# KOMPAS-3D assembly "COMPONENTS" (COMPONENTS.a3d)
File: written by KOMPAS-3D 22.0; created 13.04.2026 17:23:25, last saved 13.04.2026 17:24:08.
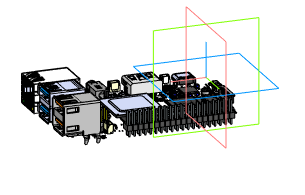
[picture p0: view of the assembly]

Document properties: Автор: Andrey; Полное имя файла: C:\Users\User1\Documents\Работа\Корпуса\Корпус Repka Pi 5\Конструкторская документация\3д модель\Repka_5_3D\COMPONENTS.a3d

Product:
- Component [assembly]: C0201  | qty 1  | source file: C0201.a3d
- Component [assembly]: C0201  | qty 293  | Комментарий: C0201; source file: C0201.a3d
- Component [assembly]: QFN50P500X500X90-33N-D  | qty 1  | Масса: 0.000177; source file: QFN50P500X500X90-33N-D.a3d
- Component [assembly]: QFN45P400X400X80-29N  | qty 1  | Масса: 0.00011; source file: QFN45P400X400X80-29N.a3d
- Component [assembly]: QFN40P500X500X90-41N  | qty 1  | Масса: 0.000173; source file: QFN40P500X500X90-41N.a3d
- Component [assembly]: JST_BM03B-SRSS-TBLFSN  | qty 1  | Масса: 0.000249; source file: JST_BM03B-SRSS-TBLFSN.a3d
- Component [assembly]: L2520  | qty 1  | Масса: 0.000033; source file: L2520.a3d
- Component [assembly]: L2520  | qty 8  | Масса: 0.000033; Комментарий: L2520; source file: L2520.a3d
- Component [assembly]: IND_201610  | qty 1  | Масса: 0.000025; source file: IND_201610.a3d
- Component [assembly]: IND_201610  | qty 5  | Масса: 0.000025; Комментарий: IND_201610; source file: IND_201610.a3d
- Component [assembly]: IND_404020  | qty 1  | Масса: 0.0002; source file: IND_404020.a3d
- Component [assembly]: C0603  | qty 1  | Масса: 0.000009; source file: C0603.a3d
- Component [assembly]: C0603  | qty 77  | Масса: 0.000009; Комментарий: C0603; source file: C0603.a3d
- Component [assembly]: SUNTECH_ST-TF-003A  | qty 1  | Масса: 0.001552; source file: SUNTECH_ST-TF-003A.a3d
- Component [assembly]: R0201  | qty 1  | source file: R0201.a3d
- Component [assembly]: R0201  | qty 213  | Комментарий: R0201; source file: R0201.a3d
- Component [assembly]: R0603  | qty 1  | Масса: 0.000004; source file: R0603.a3d
- Component [assembly]: R0603  | qty 1  | Масса: 0.000004; Комментарий: R0603; source file: R0603.a3d
- Component [assembly]: C0402  | qty 1  | Масса: 0.000002; source file: C0402.a3d
- Component [assembly]: C0402  | qty 76  | Масса: 0.000002; Комментарий: C0402; source file: C0402.a3d
- Component [assembly]: C0805  | qty 1  | Масса: 0.000027; source file: C0805.a3d
- Component [assembly]: C0805  | qty 7  | Масса: 0.000027; Комментарий: C0805; source file: C0805.a3d
- Component [assembly]: HR911130C  | qty 1  | Масса: 0.029144; source file: HR911130C.a3d
- Component [assembly]: SOT-323  | qty 1  | Масса: 0.000021; source file: SOT-323.a3d
- Component [assembly]: SOT-323  | qty 8  | Масса: 0.000021; Комментарий: SOT-323; source file: SOT-323.a3d
- Component [assembly]: BGA20C40P4X5_161X201X63  | qty 1  | Масса: 0.000011; source file: BGA20C40P4X5_161X201X63.a3d
- Component [assembly]: BGA20C40P4X5_161X201X63  | qty 2  | Масса: 0.000011; Комментарий: BGA20C40P4X5_161X201X63; source file: BGA20C40P4X5_161X201X63.a3d
- Component [assembly]: NX2016SA  | qty 1  | Масса: 0.000012; source file: NX2016SA.a3d
- Component [assembly]: NX2016SA  | qty 3  | Масса: 0.000012; Комментарий: NX2016SA; source file: NX2016SA.a3d
- Component [assembly]: BGA1088_23R00X23R00X2R00  | qty 1  | Масса: 0.006277; source file: BGA1088_23R00X23R00X2R00.a3d
- Component [assembly]: BGA200C65X80P22X12_1500X1000X114N  | qty 1  | Масса: 0.00091; source file: BGA200C65X80P22X12_1500X1000X114N.a3d
- Component [assembly]: BGA200C65X80P22X12_1500X1000X114N  | qty 1  | Масса: 0.00091; Комментарий: BGA200C65X80P22X12_1500X1000X114N; source file: BGA200C65X80P22X12_1500X1000X114N.a3d
- Component [assembly]: SOD_323  | qty 1  | Масса: 0.000016; source file: SOD_323.a3d
- Component [assembly]: SOD_323  | qty 6  | Масса: 0.000016; Комментарий: SOD_323; source file: SOD_323.a3d
- Component [assembly]: XTAL_NX3215SA-32768K-STD-MUA-8  | qty 1  | Масса: 0.000032; source file: XTAL_NX3215SA-32768K-STD-MUA-8.a3d
- Component [assembly]: SOP65P490X110-8N  | qty 1  | Масса: 0.00007; source file: SOP65P490X110-8N.a3d
- Component [detail]: SW_SMD_3_4_2  | qty 1  | Комментарий: SW_SMD_3_4_2; source file: SW_SMD_3_4_2.m3d
- Component [assembly]: SOT_23_5  | qty 1  | Масса: 0.000046; source file: SOT_23_5.a3d
- Component [assembly]: SOT_23_5  | qty 2  | Масса: 0.000046; Комментарий: SOT_23_5; source file: SOT_23_5.a3d
- Component [assembly]: L0402  | qty 1  | Масса: 0.000002; source file: L0402.a3d
- Component [detail]: TEST_POINT_060  | qty 10  | Комментарий: TEST_POINT_060; source file: TEST_POINT_060.m3d
- Component [detail]: TEST_POINT_080  | qty 14  | Комментарий: TEST_POINT_080; source file: TEST_POINT_080.m3d
- Component [assembly]: QFN68_7R00X7R00X0R80_T  | qty 1  | Масса: 0.000332; source file: QFN68_7R00X7R00X0R80_T.a3d
- Component [assembly]: GCT_FFC2A33-22-T-R_REVA  | qty 1  | Масса: 0.001036; source file: GCT_FFC2A33-22-T-R_REVA.a3d
- Component [assembly]: GCT_FFC2A33-22-T-R_REVA  | qty 1  | Масса: 0.001036; Комментарий: GCT_FFC2A33-22-T-R_REVA; source file: GCT_FFC2A33-22-T-R_REVA.a3d
- Component [assembly]: CUI_UJC-HP-3-SMT-TR  | qty 1  | Масса: 0.000312; source file: CUI_UJC-HP-3-SMT-TR.a3d
- Component [assembly]: HDMI_SMD  | qty 1  | Масса: 0.004704; source file: HDMI_SMD.a3d
- Component [assembly]: GB042-30-34PH10  | qty 1  | Масса: 0.00023; source file: GB042-30-34PH10.a3d
- Component [assembly]: SAMTEC_USBR-A-D-F-O-TH  | qty 1  | Масса: 0.021096; source file: SAMTEC_USBR-A-D-F-O-TH.a3d
- Component [assembly]: BGA153_PAD30  | qty 1  | Масса: 0.000515; source file: BGA153_PAD30.a3d
- Component [assembly]: ESD0402  | qty 1  | Масса: 0.000002; source file: ESD0402.a3d
- Component [assembly]: ESD0402  | qty 17  | Масса: 0.000002; Комментарий: ESD0402; source file: ESD0402.a3d
- Component [assembly]: 1188E1K2QTR  | qty 1  | Масса: 0.000327; source file: 1188E1K2QTR.a3d
- Component [assembly]: MOLEX_48406-0003  | qty 1  | Масса: 0.017886; source file: MOLEX_48406-0003.a3d
- Component [assembly]: LED0603  | qty 1  | Масса: 0.000005; source file: LED0603.a3d
- Component [assembly]: LED0603  | qty 1  | Масса: 0.000005; Комментарий: LED0603; source file: LED0603.a3d
- Component [assembly]: JST_BM02B-SRSS-TBLFSN  | qty 1  | Масса: 0.00021; source file: JST_BM02B-SRSS-TBLFSN.a3d
- Component [assembly]: AP6210  | qty 1  | Масса: 0.001822; source file: AP6210.a3d
- Component [assembly]: SON127P500X600X80-9N  | qty 1  | Масса: 0.000183; source file: SON127P500X600X80-9N.a3d
- Component [assembly]: GCT_FFC2A33-16-T-R_REVA  | qty 1  | Масса: 0.000865; source file: GCT_FFC2A33-16-T-R_REVA.a3d
- Component [detail]: JST_B4B-PH-K-SLFSN  | qty 1  | Масса: 0.001556; source file: JST_B4B-PH-K-SLFSN.m3d
- Component [detail]: JST_B4B-PH-K-SLFSN  | qty 1  | Масса: 0.001556; Комментарий: JST_B4B-PH-K-SLFSN; source file: JST_B4B-PH-K-SLFSN.m3d
- Component [assembly]: SAMTEC_HTSW-102-26-L-D  | qty 1  | Масса: 0.000525; source file: SAMTEC_HTSW-102-26-L-D.a3d
- Component [assembly]: JST_BM04B-SRSS-TBLFSN  | qty 1  | Масса: 0.000287; source file: JST_BM04B-SRSS-TBLFSN.a3d
- Component [assembly]: HRS_UFL-R-SMT01  | qty 1  | Масса: 0.000027; source file: HRS_UFL-R-SMT01.a3d
- Component [assembly]: PJ3420ASMT  | qty 1  | Масса: 0.001673; source file: PJ3420ASMT.a3d
- Component [assembly]: PIN_40_254  | qty 1  | Масса: 0.006833; source file: PIN_40_254.a3d
- Part/product: COMPONENTS
    Масса: 0.10509
    Комментарий: COMPONENTS

Referenced files in C:\Users\User1\Documents\Работа\Корпуса\Корпус Repka Pi 5\Конструкторская документация\3д модель\Repka_5_3D\: C0201.a3d, QFN50P500X500X90-33N-D.a3d, QFN45P400X400X80-29N.a3d, QFN40P500X500X90-41N.a3d, JST_BM03B-SRSS-TBLFSN.a3d, L2520.a3d, IND_201610.a3d, IND_404020.a3d, C0603.a3d, SUNTECH_ST-TF-003A.a3d, R0201.a3d, R0603.a3d, C0402.a3d, C0805.a3d, HR911130C.a3d, SOT-323.a3d, BGA20C40P4X5_161X201X63.a3d, NX2016SA.a3d, BGA1088_23R00X23R00X2R00.a3d, BGA200C65X80P22X12_1500X1000X114N.a3d, SOD_323.a3d, XTAL_NX3215SA-32768K-STD-MUA-8.a3d, SOP65P490X110-8N.a3d, SW_SMD_3_4_2.m3d, SOT_23_5.a3d, L0402.a3d, TEST_POINT_060.m3d, TEST_POINT_080.m3d, QFN68_7R00X7R00X0R80_T.a3d, GCT_FFC2A33-22-T-R_REVA.a3d, CUI_UJC-HP-3-SMT-TR.a3d, HDMI_SMD.a3d, GB042-30-34PH10.a3d, SAMTEC_USBR-A-D-F-O-TH.a3d, BGA153_PAD30.a3d, ESD0402.a3d, 1188E1K2QTR.a3d, MOLEX_48406-0003.a3d, LED0603.a3d, JST_BM02B-SRSS-TBLFSN.a3d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
Referenced files in C:\Users\User1\Documents\: C0201.a3d, L2520.a3d, IND_201610.a3d, C0603.a3d, R0201.a3d, R0603.a3d, C0402.a3d, C0805.a3d, SOT-323.a3d, BGA20C40P4X5_161X201X63.a3d, NX2016SA.a3d, BGA200C65X80P22X12_1500X1000X114N.a3d, SOD_323.a3d, SOT_23_5.a3d, TEST_POINT_060.m3d, TEST_POINT_080.m3d, GCT_FFC2A33-22-T-R_REVA.a3d, ESD0402.a3d, LED0603.a3d, JST_B4B-PH-K-SLFSN.m3d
